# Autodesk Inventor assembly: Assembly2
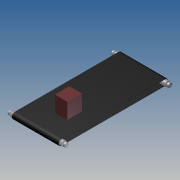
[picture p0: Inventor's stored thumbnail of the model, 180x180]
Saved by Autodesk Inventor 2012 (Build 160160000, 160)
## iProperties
Created: 2012-04
Part Number: Assembly2
Document SubType Name: Assembly
Designer: win32
Author: win32
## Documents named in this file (5)
- D:\Users\win32\Desktop\flexible part\Assembly2.iam
- F:\Mohsen\payanname\pic\poly.ipt
- F:\Mohsen\payanname\pic\bearing.ipt
- D:\Users\win32\Desktop\flexible part\belt.ipt
- D:\Users\win32\Desktop\flexible part\box.ipt
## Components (8 placed, 4 different names)
1. poly:1 — Insert:3, Insert:4, Mate:1, Mate:2, Rotation:1, Mate:4
2. poly:2 — Insert:1, Insert:2, Mate:1, Insert:5, Rotation:1, Mate:4
3. bearing:1 — Insert:2
4. bearing:2 — Insert:4
5. bearing:3 — Insert:3, Flush:1
6. bearing:4 — Insert:1, Flush:1
7. belt:1 — Insert:5, Mate:2, Mate:3, Angle:1
8. box:1 — Mate:3
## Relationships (12: Insert 5, Mate 4, Flush 1, RelateRotation 1, Angle 1)
- Insert:1: poly:2 ↔ bearing:4
- Insert:2: poly:2 ↔ bearing:1
- Insert:3: poly:1 ↔ bearing:3
- Insert:4: poly:1 ↔ bearing:2
- Mate:1: poly:1 ↔ poly:2
- Flush:1: bearing:3 ↔ bearing:4
- Insert:5: poly:2 ↔ belt:1
- Mate:2: poly:1 ↔ belt:1
- Mate:3: belt:1 ↔ box:1
- Rotation:1 [RelateRotation]: poly:1 ↔ poly:2
- Mate:4: poly:1 ↔ poly:2
- Angle:1: belt:1
